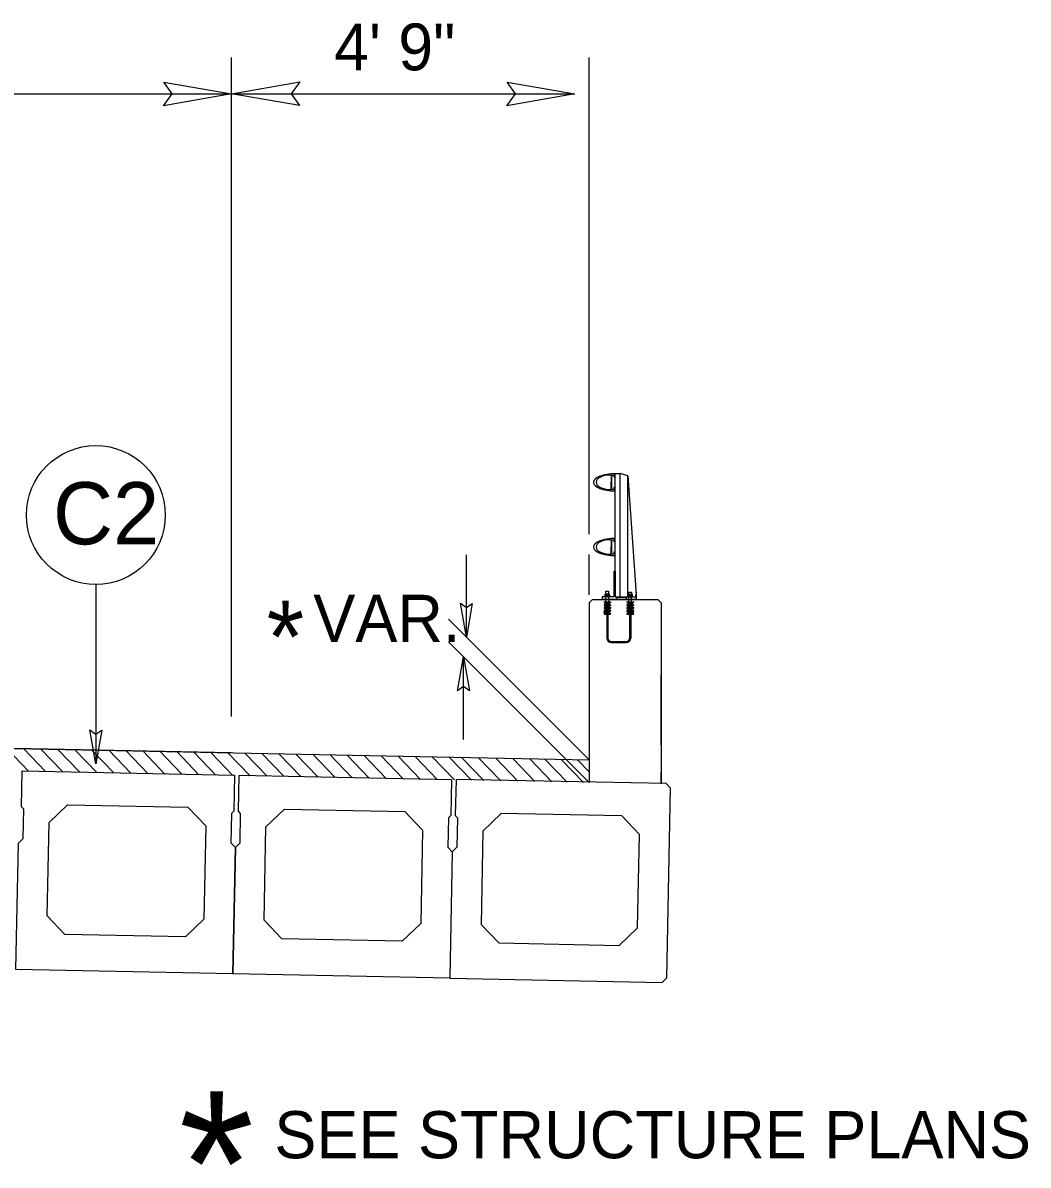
# Model space of a CAD drawing. Extents: x 573771 to 574316, y -53454 to -53190.
# Drawn here: x 574166.73 to 574194.56, y -53357.43 to -53325.81 of the extents above; entities that cross this region are included whole.
import ezdxf

# ---------------------------------------------------------------- set-up
doc = ezdxf.new("R2010")
doc.units = 0
for name, color, linetype in [('Default', 7, 'Continuous'), ('Typical ID Circle CELL', 7, 'Continuous'), ('Typical Pavement Slope CELL', 7, 'Continuous'), ('Typical Pavement Slope Information CELL', 7, 'Continuous'), ('Typical Terminator CELL', 7, 'Continuous'), ('Typical Text Grade Point CELL', 7, 'Continuous'), ('Typical Text ID Circle CELL', 7, 'Continuous')]:
    doc.layers.add(name, color=color, linetype=linetype)

msp = doc.modelspace()

# ---------------------------------------------------------------- linework, layer by layer
at = {"layer": 'Default'}
for p, q in [((574182.408, -53339.967), (574182.408, -53326.768)), ((574183.017, -53338.341), (574183.017, -53338.527)), ((574183.132, -53338.284), (574183.268, -53338.284)), ((574183.132, -53341.702), (574183.132, -53338.284)), ((574183.475, -53338.352), (574183.268, -53338.284)), ((574183.268, -53341.702), (574183.268, -53338.284)), ((574183.475, -53341.702), (574183.475, -53338.352)), ((574183.475, -53338.352), (574183.713, -53341.634)), ((574183.017, -53338.713), (574183.017, -53338.527)), ((574183.017, -53340.133), (574183.017, -53340.318)), ((574183.017, -53340.504), (574183.017, -53340.318)), ((574182.408, -53341.642), (574182.408, -53340.524)), ((574182.869, -53341.611), (574182.869, -53341.546)), ((574182.869, -53341.546), (574182.947, -53341.546)), ((574182.947, -53341.546), (574182.947, -53341.611)), ((574183.503, -53341.629), (574183.503, -53341.565)), ((574183.503, -53341.565), (574183.58, -53341.565)), ((574183.58, -53341.565), (574183.58, -53341.629)), ((574183.707, -53341.596), (574183.707, -53341.536)), ((574183.713, -53341.702), (574183.713, -53341.634)), ((574182.497, -53341.771), (574182.408, -53341.86)), ((574182.408, -53341.86), (574182.408, -53346.84)), ((574182.497, -53341.771), (574184.309, -53341.771)), ((574182.821, -53341.837), (574183.002, -53341.837)), ((574182.821, -53341.857), (574183.002, -53341.857)), ((574182.821, -53341.917), (574182.896, -53341.917)), ((574182.821, -53341.937), (574182.896, -53341.937)), ((574182.861, -53341.877), (574182.896, -53341.877)), ((574182.861, -53341.897), (574182.896, -53341.897)), ((574182.866, -53341.837), (574182.866, -53341.685)), ((574182.896, -53341.877), (574182.926, -53341.877)), ((574182.896, -53341.877), (574182.896, -53342.84)), ((574182.926, -53341.877), (574182.962, -53341.877)), ((574182.926, -53341.877), (574182.926, -53342.84)), ((574182.926, -53341.897), (574182.962, -53341.897)), ((574182.926, -53341.917), (574183.002, -53341.917)), ((574182.926, -53341.937), (574183.002, -53341.937)), ((574182.951, -53341.837), (574182.951, -53341.685)), ((574183.453, -53341.837), (574183.635, -53341.837)), ((574183.453, -53341.857), (574183.635, -53341.857)), ((574183.453, -53341.917), (574183.529, -53341.917)), ((574183.453, -53341.937), (574183.529, -53341.937)), ((574183.493, -53341.877), (574183.529, -53341.877)), ((574183.493, -53341.897), (574183.529, -53341.897)), ((574183.503, -53341.854), (574183.503, -53341.702)), ((574183.529, -53341.877), (574183.559, -53341.877)), ((574183.529, -53341.877), (574183.529, -53342.84)), ((574183.559, -53341.877), (574183.595, -53341.877)), ((574183.559, -53341.877), (574183.559, -53342.84)), ((574183.559, -53341.897), (574183.595, -53341.897)), ((574183.559, -53341.917), (574183.635, -53341.917)), ((574183.559, -53341.937), (574183.635, -53341.937)), ((574183.582, -53341.854), (574183.582, -53341.702)), ((574184.397, -53341.86), (574184.309, -53341.771)), ((574184.397, -53341.86), (574184.397, -53346.88)), ((574182.821, -53341.998), (574182.896, -53341.998)), ((574182.821, -53342.018), (574182.896, -53342.018)), ((574182.821, -53342.078), (574182.896, -53342.078)), ((574182.821, -53342.098), (574182.896, -53342.098)), ((574182.821, -53342.159), (574182.896, -53342.159)), ((574182.821, -53342.179), (574182.896, -53342.179)), ((574182.861, -53341.958), (574182.896, -53341.958)), ((574182.861, -53341.978), (574182.896, -53341.978)), ((574182.861, -53342.038), (574182.896, -53342.038)), ((574182.861, -53342.058), (574182.896, -53342.058)), ((574182.861, -53342.119), (574182.896, -53342.119)), ((574182.861, -53342.139), (574182.896, -53342.139)), ((574182.926, -53341.958), (574182.962, -53341.958)), ((574182.926, -53341.978), (574182.962, -53341.978)), ((574182.926, -53341.998), (574183.002, -53341.998)), ((574182.926, -53342.018), (574183.002, -53342.018)), ((574182.926, -53342.038), (574182.962, -53342.038)), ((574182.926, -53342.058), (574182.962, -53342.058)), ((574182.926, -53342.078), (574183.002, -53342.078)), ((574182.926, -53342.098), (574183.002, -53342.098)), ((574182.926, -53342.119), (574182.962, -53342.119)), ((574182.926, -53342.139), (574182.962, -53342.139)), ((574182.926, -53342.159), (574183.002, -53342.159)), ((574182.926, -53342.179), (574183.002, -53342.179)), ((574183.453, -53341.998), (574183.529, -53341.998)), ((574183.453, -53342.018), (574183.529, -53342.018)), ((574183.453, -53342.078), (574183.529, -53342.078)), ((574183.453, -53342.098), (574183.529, -53342.098)), ((574183.453, -53342.159), (574183.529, -53342.159)), ((574183.453, -53342.179), (574183.529, -53342.179)), ((574183.493, -53341.958), (574183.529, -53341.958)), ((574183.493, -53341.978), (574183.529, -53341.978)), ((574183.493, -53342.038), (574183.529, -53342.038)), ((574183.493, -53342.058), (574183.529, -53342.058)), ((574183.493, -53342.119), (574183.529, -53342.119)), ((574183.493, -53342.139), (574183.529, -53342.139)), ((574183.559, -53341.958), (574183.595, -53341.958)), ((574183.559, -53341.978), (574183.595, -53341.978)), ((574183.559, -53341.998), (574183.635, -53341.998)), ((574183.559, -53342.018), (574183.635, -53342.018)), ((574183.559, -53342.038), (574183.595, -53342.038)), ((574183.559, -53342.058), (574183.595, -53342.058)), ((574183.559, -53342.078), (574183.635, -53342.078)), ((574183.559, -53342.098), (574183.635, -53342.098)), ((574183.559, -53342.119), (574183.595, -53342.119)), ((574183.559, -53342.139), (574183.595, -53342.139)), ((574183.559, -53342.159), (574183.635, -53342.159)), ((574183.559, -53342.179), (574183.635, -53342.179)), ((574183.023, -53342.936), (574183.432, -53342.936)), ((574183.023, -53342.967), (574183.432, -53342.967)), ((574184.397, -53345.802), (574184.397, -53343.854)), ((574114.756, -53344.856), (574182.408, -53346.215)), ((574166.893, -53346.528), (574166.281, -53345.891)), ((574167.364, -53346.538), (574166.752, -53345.9)), ((574167.836, -53346.547), (574167.223, -53345.91)), ((574168.307, -53346.557), (574167.695, -53345.919)), ((574168.778, -53346.566), (574168.166, -53345.929)), ((574169.25, -53346.575), (574168.637, -53345.938)), ((574169.721, -53346.585), (574169.108, -53345.948)), ((574170.192, -53346.594), (574169.58, -53345.957)), ((574170.663, -53346.604), (574170.051, -53345.966)), ((574171.135, -53346.613), (574170.522, -53345.976)), ((574171.606, -53346.623), (574170.994, -53345.985)), ((574172.077, -53346.632), (574171.465, -53345.995)), ((574172.549, -53346.642), (574171.936, -53346.004)), ((574173.02, -53346.651), (574172.408, -53346.014)), ((574173.491, -53346.661), (574172.879, -53346.023)), ((574173.963, -53346.67), (574173.35, -53346.033)), ((574174.434, -53346.68), (574173.822, -53346.042)), ((574174.905, -53346.689), (574174.293, -53346.052)), ((574175.377, -53346.698), (574174.764, -53346.061)), ((574175.848, -53346.708), (574175.236, -53346.071)), ((574176.319, -53346.717), (574175.707, -53346.08)), ((574176.79, -53346.727), (574176.178, -53346.089)), ((574177.262, -53346.736), (574176.649, -53346.099)), ((574177.733, -53346.746), (574177.121, -53346.108)), ((574178.204, -53346.755), (574177.592, -53346.118)), ((574178.676, -53346.765), (574178.063, -53346.127)), ((574179.147, -53346.774), (574178.535, -53346.137)), ((574179.49, -53346.781), (574178.878, -53346.144)), ((574179.961, -53346.791), (574179.349, -53346.153)), ((574180.433, -53346.8), (574179.82, -53346.163)), ((574180.904, -53346.809), (574180.292, -53346.172)), ((574181.375, -53346.819), (574180.763, -53346.182)), ((574181.797, -53346.827), (574181.184, -53346.19)), ((574182.249, -53346.836), (574181.636, -53346.199)), ((574182.408, -53346.54), (574182.089, -53346.208)), ((574184.397, -53346.88), (574184.397, -53346.55))]:
    msp.add_line(p, q, dxfattribs=at)
for points in [[(574183.132, -53338.763), (574183.132, -53338.675), (574183.095, -53338.675), (574183.095, -53338.69), (574183.098, -53338.69), (574183.098, -53338.727), (574183.039, -53338.727), (574183.032, -53338.67), (574183.032, -53338.527), (574183.032, -53338.384), (574183.039, -53338.327), (574183.098, -53338.327), (574183.098, -53338.364), (574183.095, -53338.364), (574183.095, -53338.379), (574183.132, -53338.379), (574183.132, -53338.29)], [(574183.132, -53340.555), (574183.132, -53340.466), (574183.095, -53340.466), (574183.095, -53340.481), (574183.098, -53340.481), (574183.098, -53340.518), (574183.039, -53340.518), (574183.032, -53340.461), (574183.032, -53340.318), (574183.032, -53340.175), (574183.039, -53340.119), (574183.098, -53340.119), (574183.098, -53340.155), (574183.095, -53340.155), (574183.095, -53340.17), (574183.132, -53340.17), (574183.132, -53340.081)], [(574182.781, -53341.771), (574182.781, -53341.685), (574183.097, -53341.685), (574183.097, -53340.984), (574183.132, -53340.984), (574183.132, -53341.702), (574183.697, -53341.702), (574183.697, -53341.652), (574183.713, -53341.652), (574183.713, -53341.771), (574183.441, -53341.771), (574183.441, -53341.724), (574183.166, -53341.724), (574183.166, -53341.771), (574182.781, -53341.771)], [(574182.851, -53341.671), (574182.851, -53341.621), (574182.86, -53341.611), (574182.957, -53341.611), (574182.966, -53341.621), (574182.966, -53341.671), (574182.851, -53341.671), (574182.89, -53341.671), (574182.89, -53341.621), (574182.879, -53341.611), (574182.89, -53341.621), (574182.899, -53341.611), (574182.919, -53341.611), (574182.928, -53341.621), (574182.928, -53341.671), (574182.928, -53341.621), (574182.937, -53341.611)], [(574183.484, -53341.688), (574183.484, -53341.638), (574183.494, -53341.629), (574183.589, -53341.629), (574183.6, -53341.638), (574183.6, -53341.688), (574183.484, -53341.688), (574183.523, -53341.688), (574183.523, -53341.638), (574183.513, -53341.629), (574183.523, -53341.638), (574183.532, -53341.629), (574183.552, -53341.629), (574183.561, -53341.638), (574183.561, -53341.688), (574183.561, -53341.638), (574183.571, -53341.629)], [(574182.82, -53341.837), (574182.82, -53341.857), (574182.861, -53341.877), (574182.861, -53341.897), (574182.82, -53341.917), (574182.82, -53341.937), (574182.861, -53341.958), (574182.861, -53341.978), (574182.82, -53341.998), (574182.82, -53342.018), (574182.861, -53342.038), (574182.861, -53342.058), (574182.82, -53342.078), (574182.82, -53342.098), (574182.861, -53342.119), (574182.861, -53342.139), (574182.82, -53342.159), (574182.82, -53342.179)], [(574182.829, -53341.686), (574182.829, -53341.67), (574182.907, -53341.67), (574182.986, -53341.67), (574182.986, -53341.686)], [(574183.002, -53341.837), (574183.002, -53341.857), (574182.962, -53341.877), (574182.962, -53341.897), (574183.002, -53341.917), (574183.002, -53341.937), (574182.962, -53341.958), (574182.962, -53341.978), (574183.002, -53341.998), (574183.002, -53342.018), (574182.962, -53342.038), (574182.962, -53342.058), (574183.002, -53342.078), (574183.002, -53342.098), (574182.962, -53342.119), (574182.962, -53342.139), (574183.002, -53342.159), (574183.002, -53342.179)], [(574183.453, -53341.837), (574183.453, -53341.857), (574183.493, -53341.877), (574183.493, -53341.897), (574183.453, -53341.917), (574183.453, -53341.937), (574183.493, -53341.958), (574183.493, -53341.978), (574183.453, -53341.998), (574183.453, -53342.018), (574183.493, -53342.038), (574183.493, -53342.058), (574183.453, -53342.078), (574183.453, -53342.098), (574183.493, -53342.119), (574183.493, -53342.139), (574183.453, -53342.159), (574183.453, -53342.179)], [(574183.464, -53341.704), (574183.464, -53341.688), (574183.542, -53341.688), (574183.62, -53341.688), (574183.62, -53341.704)], [(574183.635, -53341.837), (574183.635, -53341.857), (574183.595, -53341.877), (574183.595, -53341.897), (574183.635, -53341.917), (574183.635, -53341.937), (574183.595, -53341.958), (574183.595, -53341.978), (574183.635, -53341.998), (574183.635, -53342.018), (574183.595, -53342.038), (574183.595, -53342.058), (574183.635, -53342.078), (574183.635, -53342.098), (574183.595, -53342.119), (574183.595, -53342.139), (574183.635, -53342.159), (574183.635, -53342.179)]]:
    msp.add_lwpolyline(points, dxfattribs=at)
for points in [[(574166.542, -53352.018), (574166.612, -53348.515), (574166.74, -53348.393), (574166.756, -53347.58), (574166.695, -53347.516), (574166.715, -53346.515), (574172.593, -53346.633), (574172.573, -53347.633), (574172.51, -53347.695), (574172.493, -53348.508), (574172.616, -53348.635), (574172.546, -53352.138)], [(574172.546, -53352.138), (574172.616, -53348.635), (574172.744, -53348.513), (574172.76, -53347.7), (574172.698, -53347.636), (574172.718, -53346.635), (574178.597, -53346.753), (574178.577, -53347.753), (574178.514, -53347.815), (574178.497, -53348.628), (574178.62, -53348.755), (574178.55, -53352.257)], [(574184.556, -53352.252), (574184.661, -53346.999), (574184.539, -53346.871), (574178.722, -53346.755), (574178.702, -53347.756), (574178.764, -53347.82), (574178.747, -53348.633), (574178.62, -53348.755), (574178.55, -53352.257), (574184.429, -53352.375)], [(574167.896, -53351.044), (574167.406, -53350.533), (574167.458, -53347.948), (574167.968, -53347.458), (574171.303, -53347.525), (574171.794, -53348.035), (574171.742, -53350.62), (574171.232, -53351.11)], [(574173.9, -53351.164), (574173.41, -53350.653), (574173.462, -53348.068), (574173.972, -53347.578), (574177.307, -53347.645), (574177.798, -53348.155), (574177.746, -53350.74), (574177.236, -53351.23)], [(574183.24, -53351.35), (574183.75, -53350.86), (574183.802, -53348.275), (574183.311, -53347.764), (574179.976, -53347.698), (574179.465, -53348.188), (574179.414, -53350.773), (574179.904, -53351.283)]]:
    msp.add_lwpolyline(points, close=True, dxfattribs=at)
for centre in [(574182.836, -53342.129), (574183.619, -53342.129)]:
    msp.add_circle(centre, 0.0151, dxfattribs=at)
for centre, radius, start, end in [((574183.003, -53338.341), 0.0142, 0, 90), ((574183.003, -53338.712), 0.0142, 270, 0), ((574183.003, -53340.133), 0.0142, 0, 90), ((574183.003, -53340.504), 0.0142, 270, 0), ((574183.023, -53342.84), 0.127, 180, 270), ((574183.023, -53342.84), 0.0969, 180, 270), ((574183.432, -53342.84), 0.0969, 270, 0), ((574183.432, -53342.84), 0.127, 270, 0)]:
    msp.add_arc(centre, radius, start, end, dxfattribs=at)
for centre, major_axis, ratio, start_param, end_param in [((574183.132, -53338.527), (-0.607, 0), 0.39036, 4.712404, 6.283584), ((574183.003, -53338.527), (-0.403, 0), 0.495501, 4.712489, 6.283652), ((574183.132, -53338.527), (-0.607, 0), 0.39036, 0.000398, 1.570782), ((574183.003, -53338.527), (-0.403, 0), 0.495501, 0.000467, 1.570696), ((574183.132, -53340.318), (-0.607, 0), 0.39036, 4.712404, 6.283584), ((574183.132, -53340.318), (-0.607, 0), 0.39036, 0.000398, 1.570782), ((574183.003, -53340.318), (-0.403, 0), 0.495501, 4.712489, 6.283652), ((574183.003, -53340.318), (-0.403, 0), 0.495501, 0.000467, 1.570696)]:
    msp.add_ellipse(centre, major_axis=major_axis, ratio=ratio, start_param=start_param, end_param=end_param, dxfattribs=at)
at = {"layer": 'Typical ID Circle CELL'}
msp.add_line((574168.753, -53341.356), (574168.753, -53346.326), dxfattribs=at)
msp.add_circle((574168.753, -53339.433), 1.923, dxfattribs=at)
at = {"layer": 'Typical Pavement Slope CELL'}
msp.add_line((574172.503, -53346.014), (574148.511, -53345.534), dxfattribs=at)
at = {"layer": 'Typical Pavement Slope Information CELL'}
for p, q in [((574172.511, -53345.014), (574172.511, -53326.768)), ((574148.511, -53327.768), (574172.511, -53327.768)), ((574172.511, -53327.768), (574182.011, -53327.768)), ((574179.01, -53342.817), (574179.01, -53340.532)), ((574182.408, -53346.215), (574178.51, -53342.317)), ((574182.408, -53346.84), (574178.51, -53342.942)), ((574178.929, -53345.646), (574178.929, -53343.361))]:
    msp.add_line(p, q, dxfattribs=at)
at = {"layer": 'Typical Terminator CELL'}
for points in [[(574170.637, -53327.445), (574172.511, -53327.768), (574170.626, -53328.101), (574170.866, -53327.768)], [(574174.386, -53328.091), (574172.511, -53327.768), (574174.397, -53327.435), (574174.157, -53327.768)], [(574180.137, -53327.445), (574182.011, -53327.768), (574180.126, -53328.101), (574180.366, -53327.768)], [(574179.172, -53341.88), (574179.01, -53342.817), (574178.844, -53341.874), (574179.01, -53341.994)], [(574178.768, -53344.298), (574178.929, -53343.361), (574179.096, -53344.303), (574178.929, -53344.184)], [(574168.915, -53345.389), (574168.753, -53346.326), (574168.587, -53345.384), (574168.753, -53345.504)]]:
    msp.add_lwpolyline(points, close=True, dxfattribs=at)

# ---------------------------------------------------------------- texts
at = {"layer": 'Typical Pavement Slope Information CELL'}
msp.add_text('4\' 9"', height=1.2952, dxfattribs=at).set_placement((574175.35, -53327.12))
at = {"layer": 'Typical Text Grade Point CELL'}
for s, height, p in [('*', 2, (574173.481, -53343.808)), ('VAR.', 1.305, (574174.772, -53342.947)), ('*', 4, (574171.049, -53359.393)), ('SEE STRUCTURE PLANS', 1.30495, (574173.694, -53357.244))]:
    msp.add_text(s, height=height, dxfattribs=at).set_placement(p)
at = {"layer": 'Typical Text ID Circle CELL'}
msp.add_text('C2', height=1.7216, dxfattribs=at).set_placement((574167.566, -53340.245))

doc.saveas('drawing.dxf')
